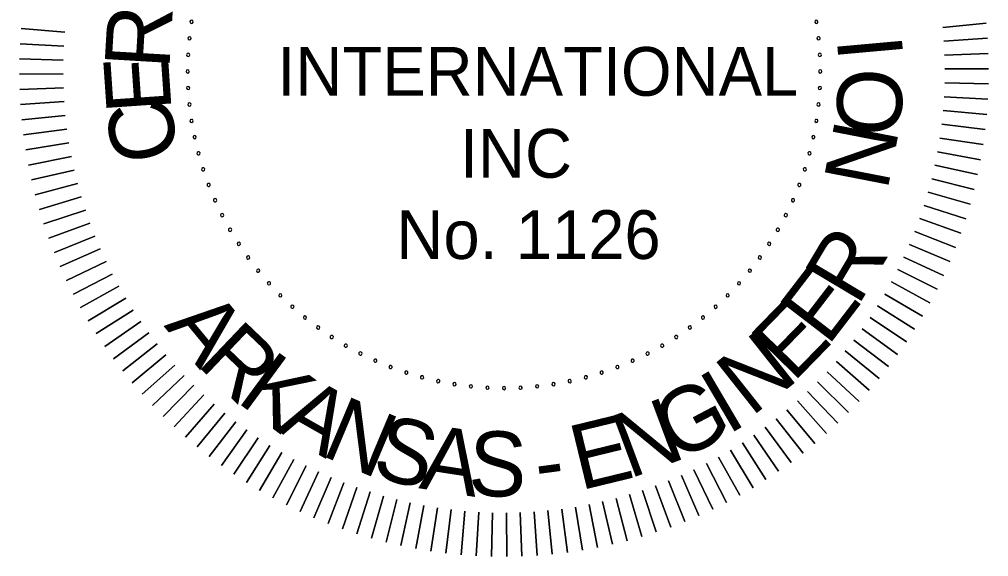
# Model space of a CAD drawing. Extents: x -12863 to 18921, y -8840 to 11152.
# Drawn here: x 10547 to 13036, y -8840 to -7462 of the extents above; entities that cross this region are included whole.
import ezdxf

# ---------------------------------------------------------------- set-up
doc = ezdxf.new("R2010")
doc.units = 0
doc.layers.add('Level 47', color=7, linetype='Continuous')

msp = doc.modelspace()

# ---------------------------------------------------------------- linework, layer by layer
at = {"layer": 'Level 47'}
for points in [[(10664.2, -7495.2), (10552.4, -7485.3)], [(10552.4, -7485.3), (10664.2, -7495.2)], [(13030.1, -7471.5), (12918.4, -7482.7)], [(12918.4, -7482.7), (13030.1, -7471.5)], [(13033.4, -7510.4), (12921.4, -7518.1)], [(12921.4, -7518.1), (13033.4, -7510.4)], [(10661.6, -7530.7), (10549.5, -7524.3)], [(10549.5, -7524.3), (10661.6, -7530.7)], [(10660.1, -7566.2), (10547.9, -7563.3)], [(10547.9, -7563.3), (10660.1, -7566.2)], [(13035.5, -7549.5), (12923.3, -7553.6)], [(12923.3, -7553.6), (13035.5, -7549.5)], [(13036.3, -7588.6), (12924.1, -7589.2)], [(12924.1, -7589.2), (13036.3, -7588.6)], [(10659.7, -7601.8), (10547.5, -7602.4)], [(10547.5, -7602.4), (10659.7, -7601.8)], [(10660.5, -7637.4), (10548.3, -7641.5)], [(10548.3, -7641.5), (10660.5, -7637.4)], [(13035.9, -7627.6), (12923.7, -7624.7)], [(12923.7, -7624.7), (13035.9, -7627.6)], [(13034.3, -7666.7), (12922.2, -7660.3)], [(12922.2, -7660.3), (13034.3, -7666.7)], [(10662.4, -7672.9), (10550.4, -7680.5)], [(10550.4, -7680.5), (10662.4, -7672.9)], [(10665.3, -7708.3), (10553.7, -7719.5)], [(10553.7, -7719.5), (10665.3, -7708.3)], [(13031.4, -7705.7), (12919.6, -7695.8)], [(12919.6, -7695.8), (13031.4, -7705.7)], [(13027.3, -7744.6), (12915.9, -7731.1)], [(12915.9, -7731.1), (13027.3, -7744.6)], [(10669.4, -7743.7), (10558.2, -7758.3)], [(10558.2, -7758.3), (10669.4, -7743.7)], [(10674.6, -7778.8), (10563.9, -7797)], [(10563.9, -7797), (10674.6, -7778.8)], [(13022, -7783.3), (12911.1, -7766.4)], [(12911.1, -7766.4), (13022, -7783.3)], [(10681, -7813.8), (10570.8, -7835.5)], [(10570.8, -7835.5), (10681, -7813.8)], [(13015.5, -7821.9), (12905.2, -7801.4)], [(12905.2, -7801.4), (13015.5, -7821.9)], [(13007.8, -7860.2), (12898.2, -7836.3)], [(12898.2, -7836.3), (13007.8, -7860.2)], [(10688.4, -7848.6), (10579, -7873.7)], [(10579, -7873.7), (10688.4, -7848.6)], [(10696.9, -7883.2), (10588.3, -7911.7)], [(10588.3, -7911.7), (10696.9, -7883.2)], [(12998.9, -7898.2), (12890.1, -7870.9)], [(12890.1, -7870.9), (12998.9, -7898.2)], [(12988.8, -7936), (12880.9, -7905.3)], [(12880.9, -7905.3), (12988.8, -7936)], [(10706.4, -7917.4), (10598.8, -7949.3)], [(10598.8, -7949.3), (10706.4, -7917.4)], [(10717.1, -7951.4), (10610.5, -7986.6)], [(10610.5, -7986.6), (10717.1, -7951.4)], [(12977.5, -7973.4), (12870.6, -7939.4)], [(12870.6, -7939.4), (12977.5, -7973.4)], [(10728.8, -7984.9), (10623.4, -8023.5)], [(10623.4, -8023.5), (10728.8, -7984.9)], [(12965.1, -8010.5), (12859.3, -7973.1)], [(12859.3, -7973.1), (12965.1, -8010.5)], [(12951.5, -8047.1), (12846.9, -8006.4)], [(12846.9, -8006.4), (12951.5, -8047.1)], [(10741.5, -8018.1), (10637.4, -8060)], [(10637.4, -8060), (10741.5, -8018.1)], [(10755.3, -8050.9), (10652.6, -8096.1)], [(10652.6, -8096.1), (10755.3, -8050.9)], [(12936.7, -8083.3), (12833.4, -8039.3)], [(12833.4, -8039.3), (12936.7, -8083.3)], [(10770.2, -8083.3), (10668.9, -8131.6)], [(10668.9, -8131.6), (10770.2, -8083.3)], [(12920.8, -8119.1), (12819, -8071.8)], [(12819, -8071.8), (12920.8, -8119.1)], [(12903.8, -8154.3), (12803.5, -8103.9)], [(12803.5, -8103.9), (12903.8, -8154.3)], [(10786, -8115.1), (10686.3, -8166.6)], [(10686.3, -8166.6), (10786, -8115.1)], [(12885.7, -8188.9), (12787.1, -8135.4)], [(12787.1, -8135.4), (12885.7, -8188.9)], [(10802.8, -8146.4), (10704.8, -8201.1)], [(10704.8, -8201.1), (10802.8, -8146.4)], [(10820.6, -8177.2), (10724.3, -8234.9)], [(10724.3, -8234.9), (10820.6, -8177.2)], [(12866.5, -8223), (12769.6, -8166.4)], [(12769.6, -8166.4), (12866.5, -8223)], [(10839.3, -8207.5), (10744.9, -8268.1)], [(10744.9, -8268.1), (10839.3, -8207.5)], [(12846.3, -8256.4), (12751.2, -8196.8)], [(12751.2, -8196.8), (12846.3, -8256.4)], [(10859, -8237.1), (10766.6, -8300.7)], [(10766.6, -8300.7), (10859, -8237.1)], [(12825, -8289.2), (12731.8, -8226.6)], [(12731.8, -8226.6), (12825, -8289.2)], [(12802.7, -8321.3), (12711.5, -8255.9)], [(12711.5, -8255.9), (12802.7, -8321.3)], [(10879.7, -8266.1), (10789.2, -8332.5)], [(10789.2, -8332.5), (10879.7, -8266.1)], [(12779.4, -8352.7), (12690.3, -8284.4)], [(12690.3, -8284.4), (12779.4, -8352.7)], [(10901.2, -8294.4), (10812.9, -8363.7)], [(10812.9, -8363.7), (10901.2, -8294.4)], [(12755.1, -8383.4), (12668.3, -8312.3)], [(12668.3, -8312.3), (12755.1, -8383.4)], [(10923.6, -8322), (10837.5, -8394)], [(10837.5, -8394), (10923.6, -8322)], [(10946.8, -8348.9), (10863, -8423.6)], [(10863, -8423.6), (10946.8, -8348.9)], [(12729.9, -8413.2), (12645.3, -8339.5)], [(12645.3, -8339.5), (12729.9, -8413.2)], [(10970.9, -8375.1), (10889.5, -8452.4)], [(10889.5, -8452.4), (10970.9, -8375.1)], [(12703.8, -8442.3), (12621.5, -8365.9)], [(12621.5, -8365.9), (12703.8, -8442.3)], [(10995.8, -8400.5), (10916.9, -8480.3)], [(10916.9, -8480.3), (10995.8, -8400.5)], [(12676.7, -8470.5), (12596.9, -8391.6)], [(12596.9, -8391.6), (12676.7, -8470.5)], [(11021.5, -8425.1), (10945.1, -8507.4)], [(10945.1, -8507.4), (11021.5, -8425.1)], [(12648.8, -8497.9), (12571.5, -8416.5)], [(12571.5, -8416.5), (12648.8, -8497.9)], [(10974.2, -8533.5), (11047.9, -8448.9)], [(11047.9, -8448.9), (10974.2, -8533.5)], [(12620, -8524.3), (12545.3, -8440.6)], [(12545.3, -8440.6), (12620, -8524.3)], [(11004, -8558.7), (11075.1, -8471.9)], [(11075.1, -8471.9), (11004, -8558.7)], [(12560.1, -8574.5), (12490.8, -8486.2)], [(12490.8, -8486.2), (12560.1, -8574.5)], [(12590.4, -8549.9), (12518.4, -8463.8)], [(12518.4, -8463.8), (12590.4, -8549.9)], [(11034.7, -8583), (11103, -8493.9)], [(11103, -8493.9), (11034.7, -8583)], [(12528.9, -8598.2), (12462.5, -8507.7)], [(12462.5, -8507.7), (12528.9, -8598.2)], [(11066.1, -8606.3), (11131.5, -8515.1)], [(11131.5, -8515.1), (11066.1, -8606.3)], [(11098.2, -8628.6), (11160.7, -8535.4)], [(11160.7, -8535.4), (11098.2, -8628.6)], [(12497.1, -8620.8), (12433.5, -8528.3)], [(12433.5, -8528.3), (12497.1, -8620.8)], [(11131, -8649.9), (11190.6, -8554.8)], [(11190.6, -8554.8), (11131, -8649.9)], [(12464.5, -8642.5), (12403.9, -8548)], [(12403.9, -8548), (12464.5, -8642.5)], [(11164.4, -8670.1), (11221, -8573.2)], [(11221, -8573.2), (11164.4, -8670.1)], [(12397.5, -8682.6), (12342.8, -8584.6)], [(12342.8, -8584.6), (12397.5, -8682.6)], [(12431.3, -8663.1), (12373.6, -8566.8)], [(12373.6, -8566.8), (12431.3, -8663.1)], [(11198.5, -8689.3), (11252, -8590.7)], [(11252, -8590.7), (11198.5, -8689.3)], [(11233.1, -8707.4), (11283.5, -8607.1)], [(11283.5, -8607.1), (11233.1, -8707.4)], [(12363, -8701.1), (12311.5, -8601.4)], [(12311.5, -8601.4), (12363, -8701.1)], [(11268.3, -8724.4), (11315.5, -8622.6)], [(11315.5, -8622.6), (11268.3, -8724.4)], [(12292.5, -8734.8), (12247.3, -8632)], [(12247.3, -8632), (12292.5, -8734.8)], [(12328, -8718.5), (12279.7, -8617.2)], [(12279.7, -8617.2), (12328, -8718.5)], [(11304, -8740.3), (11348, -8637.1)], [(11348, -8637.1), (11304, -8740.3)], [(11340.2, -8755.1), (11381, -8650.5)], [(11381, -8650.5), (11340.2, -8755.1)], [(12219.9, -8764), (12181.3, -8658.6)], [(12181.3, -8658.6), (12219.9, -8764)], [(12256.4, -8749.9), (12214.5, -8645.8)], [(12214.5, -8645.8), (12256.4, -8749.9)], [(11376.9, -8768.7), (11414.3, -8662.9)], [(11414.3, -8662.9), (11376.9, -8768.7)], [(11413.9, -8781.1), (11448, -8674.2)], [(11448, -8674.2), (11413.9, -8781.1)], [(11451.4, -8792.4), (11482.1, -8684.5)], [(11482.1, -8684.5), (11451.4, -8792.4)], [(12145.7, -8788.5), (12113.8, -8680.9)], [(12113.8, -8680.9), (12145.7, -8788.5)], [(12183, -8776.8), (12147.8, -8670.3)], [(12147.8, -8670.3), (12183, -8776.8)], [(11489.1, -8802.5), (11516.4, -8693.7)], [(11516.4, -8693.7), (11489.1, -8802.5)], [(11527.2, -8811.4), (11551.1, -8701.8)], [(11551.1, -8701.8), (11527.2, -8811.4)], [(11565.5, -8819.1), (11585.9, -8708.8)], [(11585.9, -8708.8), (11565.5, -8819.1)], [(12031.9, -8816.5), (12010.2, -8706.4)], [(12010.2, -8706.4), (12031.9, -8816.5)], [(12070.1, -8808.4), (12045, -8699)], [(12045, -8699), (12070.1, -8808.4)], [(12108.1, -8799.1), (12079.6, -8690.5)], [(12079.6, -8690.5), (12108.1, -8799.1)], [(11604.1, -8825.6), (11621, -8714.7)], [(11621, -8714.7), (11604.1, -8825.6)], [(11642.8, -8830.9), (11656.3, -8719.5)], [(11656.3, -8719.5), (11642.8, -8830.9)], [(11681.7, -8835), (11691.6, -8723.2)], [(11691.6, -8723.2), (11681.7, -8835)], [(11720.7, -8837.9), (11727.1, -8725.8)], [(11727.1, -8725.8), (11720.7, -8837.9)], [(11759.7, -8839.5), (11762.6, -8727.3)], [(11762.6, -8727.3), (11759.7, -8839.5)], [(11798.8, -8839.9), (11798.2, -8727.7)], [(11798.2, -8727.7), (11798.8, -8839.9)], [(11837.9, -8839.1), (11833.8, -8726.9)], [(11833.8, -8726.9), (11837.9, -8839.1)], [(11876.9, -8837), (11869.3, -8725)], [(11869.3, -8725), (11876.9, -8837)], [(11915.9, -8833.7), (11904.7, -8722)], [(11904.7, -8722), (11915.9, -8833.7)], [(11954.7, -8829.2), (11940, -8717.9)], [(11940, -8717.9), (11954.7, -8829.2)], [(11993.4, -8823.5), (11975.2, -8712.7)], [(11975.2, -8712.7), (11993.4, -8823.5)]]:
    msp.add_lwpolyline(points, dxfattribs=at)
for centre, start, end in [((10989.7, -7468.4), 81, 261), ((10989.7, -7468.4), 261, 81), ((12594, -7468.4), 99, 279), ((12594, -7468.4), 279, 99), ((10984.2, -7510.6), 84, 264), ((10984.2, -7510.6), 264, 84), ((12599.6, -7510.6), 96, 276), ((12599.6, -7510.6), 276, 96), ((10980.9, -7553), 87, 267), ((10980.9, -7553), 267, 87), ((12602.9, -7553), 93, 273), ((12602.9, -7553), 273, 93), ((10979.7, -7595.5), 90, 270), ((10979.7, -7595.5), 270, 90), ((12604, -7595.5), 90, 270), ((12604, -7595.5), 270, 90), ((10980.9, -7638), 93, 273), ((10980.9, -7638), 273, 93), ((12602.9, -7638), 87, 267), ((12602.9, -7638), 267, 87), ((10984.2, -7680.4), 96, 276), ((10984.2, -7680.4), 276, 96), ((12599.6, -7680.4), 84, 264), ((12599.6, -7680.4), 264, 84), ((10989.7, -7722.5), 99, 279), ((10989.7, -7722.5), 279, 99), ((12594, -7722.5), 81, 261), ((12594, -7722.5), 261, 81), ((10997.5, -7764.3), 102, 282), ((10997.5, -7764.3), 282, 102), ((12586.3, -7764.3), 78, 258), ((12586.3, -7764.3), 258, 78), ((11007.4, -7805.7), 105, 285), ((11007.4, -7805.7), 285, 105), ((12576.4, -7805.7), 75, 255), ((12576.4, -7805.7), 255, 75), ((11019.5, -7846.5), 108, 288), ((11019.5, -7846.5), 288, 108), ((12564.3, -7846.5), 72, 252), ((12564.3, -7846.5), 252, 72), ((11033.7, -7886.5), 111, 291), ((11033.7, -7886.5), 291, 111), ((12550.1, -7886.5), 69, 249), ((12550.1, -7886.5), 249, 69), ((11050, -7925.8), 114, 294), ((11050, -7925.8), 294, 114), ((12533.8, -7925.8), 66, 246), ((12533.8, -7925.8), 246, 66), ((11068.3, -7964.2), 117, 297), ((11068.3, -7964.2), 297, 117), ((12515.5, -7964.2), 63, 243), ((12515.5, -7964.2), 243, 63), ((11088.5, -8001.6), 120, 300), ((11088.5, -8001.6), 300, 120), ((12495.2, -8001.6), 60, 240), ((12495.2, -8001.6), 240, 60), ((11110.8, -8037.8), 123, 303), ((11110.8, -8037.8), 303, 123), ((12473, -8037.8), 57, 237), ((12473, -8037.8), 237, 57), ((11134.8, -8072.9), 126, 306), ((11134.8, -8072.9), 306, 126), ((12448.9, -8072.9), 54, 234), ((12448.9, -8072.9), 234, 54), ((11160.7, -8106.6), 129, 309), ((11160.7, -8106.6), 309, 129), ((12423, -8106.6), 51, 231), ((12423, -8106.6), 231, 51), ((11188.3, -8138.9), 132, 312), ((11188.3, -8138.9), 312, 132), ((12395.4, -8138.9), 48, 228), ((12395.4, -8138.9), 228, 48), ((11217.6, -8169.8), 135, 315), ((11217.6, -8169.8), 315, 135), ((12366.2, -8169.8), 45, 225), ((12366.2, -8169.8), 225, 45), ((11248.5, -8199), 138, 318), ((11248.5, -8199), 318, 138), ((12335.3, -8199), 42, 222), ((12335.3, -8199), 222, 42), ((11280.8, -8226.6), 141, 321), ((11280.8, -8226.6), 321, 141), ((12303, -8226.6), 39, 219), ((12303, -8226.6), 219, 39), ((11314.5, -8252.5), 144, 324), ((11314.5, -8252.5), 324, 144), ((12269.3, -8252.5), 36, 216), ((12269.3, -8252.5), 216, 36), ((11349.6, -8276.6), 147, 327), ((11349.6, -8276.6), 327, 147), ((12234.2, -8276.6), 33, 213), ((12234.2, -8276.6), 213, 33), ((11385.8, -8298.8), 150, 330), ((11385.8, -8298.8), 330, 150), ((12198, -8298.8), 30, 210), ((12198, -8298.8), 210, 30), ((11423.2, -8319.1), 153, 333), ((11423.2, -8319.1), 333, 153), ((11461.6, -8337.4), 156, 336), ((11461.6, -8337.4), 336, 156), ((12122.2, -8337.4), 24, 204), ((12122.2, -8337.4), 204, 24), ((12160.6, -8319.1), 27, 207), ((12160.6, -8319.1), 207, 27), ((11500.8, -8353.7), 159, 339), ((11500.8, -8353.7), 339, 159), ((12082.9, -8353.7), 21, 201), ((12082.9, -8353.7), 201, 21), ((11540.9, -8367.9), 162, 342), ((11540.9, -8367.9), 342, 162), ((11581.7, -8380), 165, 345), ((11581.7, -8380), 345, 165), ((11623, -8389.9), 348, 168), ((11960.7, -8389.9), 12, 192), ((12002.1, -8380), 15, 195), ((12002.1, -8380), 195, 15), ((12042.9, -8367.9), 18, 198), ((12042.9, -8367.9), 198, 18), ((11623, -8389.9), 168, 348), ((11664.8, -8397.6), 351, 171), ((11664.8, -8397.6), 171, 351), ((11707, -8403.2), 174, 354), ((11707, -8403.2), 354, 174), ((11749.4, -8406.5), 357, 177), ((11749.4, -8406.5), 177, 357), ((11791.9, -8407.6), 0, 180), ((11791.9, -8407.6), 180, 0), ((11834.4, -8406.5), 3, 183), ((11834.4, -8406.5), 183, 3), ((11876.8, -8403.2), 6, 186), ((11876.8, -8403.2), 186, 6), ((11918.9, -8397.6), 9, 189), ((11918.9, -8397.6), 189, 9), ((11960.7, -8389.9), 192, 12)]:
    msp.add_arc(centre, 4.17, start, end, dxfattribs=at)

# ---------------------------------------------------------------- texts
for s, rotation, p in [('R', 86.6268, (10932.4, -7591.8)), ('I', 275.1216, (12646, -7511.4)), ('E', 93.9203, (10938.6, -7695.9)), ('O', 267.0743, (12651.8, -7583)), ('C', 101.2137, (10959.9, -7811.8)), ('N', 259.0269, (12643.1, -7714.1)), ('R', 59.2262, (12700.6, -8199.9)), ('E', 52.4765, (12623.2, -8302.5)), ('E', 45.7268, (12534.4, -8395.3)), ('A', 309.5859, (10917.2, -8248.1)), ('R', 316.3356, (11000, -8346.4)), ('N', 38.4196, (12426.6, -8483.2)), ('K', 323.6428, (11101.9, -8441)), ('I', 30.5495, (12366.1, -8529.2)), ('A', 330.3925, (11206.1, -8516.3)), ('G', 27.7404, (12234.3, -8599.1)), ('N', 337.1422, (11318.4, -8578.7)), ('N', 20.4332, (12113, -8641.2)), ('S', 344.4494, (11447.3, -8631)), ('E', 13.6835, (11987.3, -8670.6)), ('A', 351.1991, (11571.4, -8664.3)), ('S', 357.9489, (11698.5, -8682.8)), ('-', 7.5077, (11880.4, -8683.2))]:
    msp.add_text(s, height=166.7, rotation=rotation, dxfattribs=at).set_placement(p)
for s, height, p in [(' INTERNATIONAL', 125.016, (11163.5, -7657.9)), ('INC', 125.02, (11678.7, -7868.2)), (' No. 1126', 125.02, (11469.2, -8076.5))]:
    msp.add_text(s, height=height, dxfattribs=at).set_placement(p)

doc.saveas('drawing.dxf')
